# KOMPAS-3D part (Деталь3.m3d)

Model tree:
1. Эскиз:1
2. Операция выдавливания:1
     Расстояние 1 = 15; Расстояние 2 = 60
3. Эскиз:2
4. Операция выдавливания:2
     Расстояние 1 = 25; Расстояние 2 = 60
5. Эскиз:3
6. Эскиз:4
7. Эскиз:5
8. Операция выдавливания:3
     Расстояние 1 = 75; Расстояние 2 = 60
9. Эскиз:6
10. Эскиз:7
